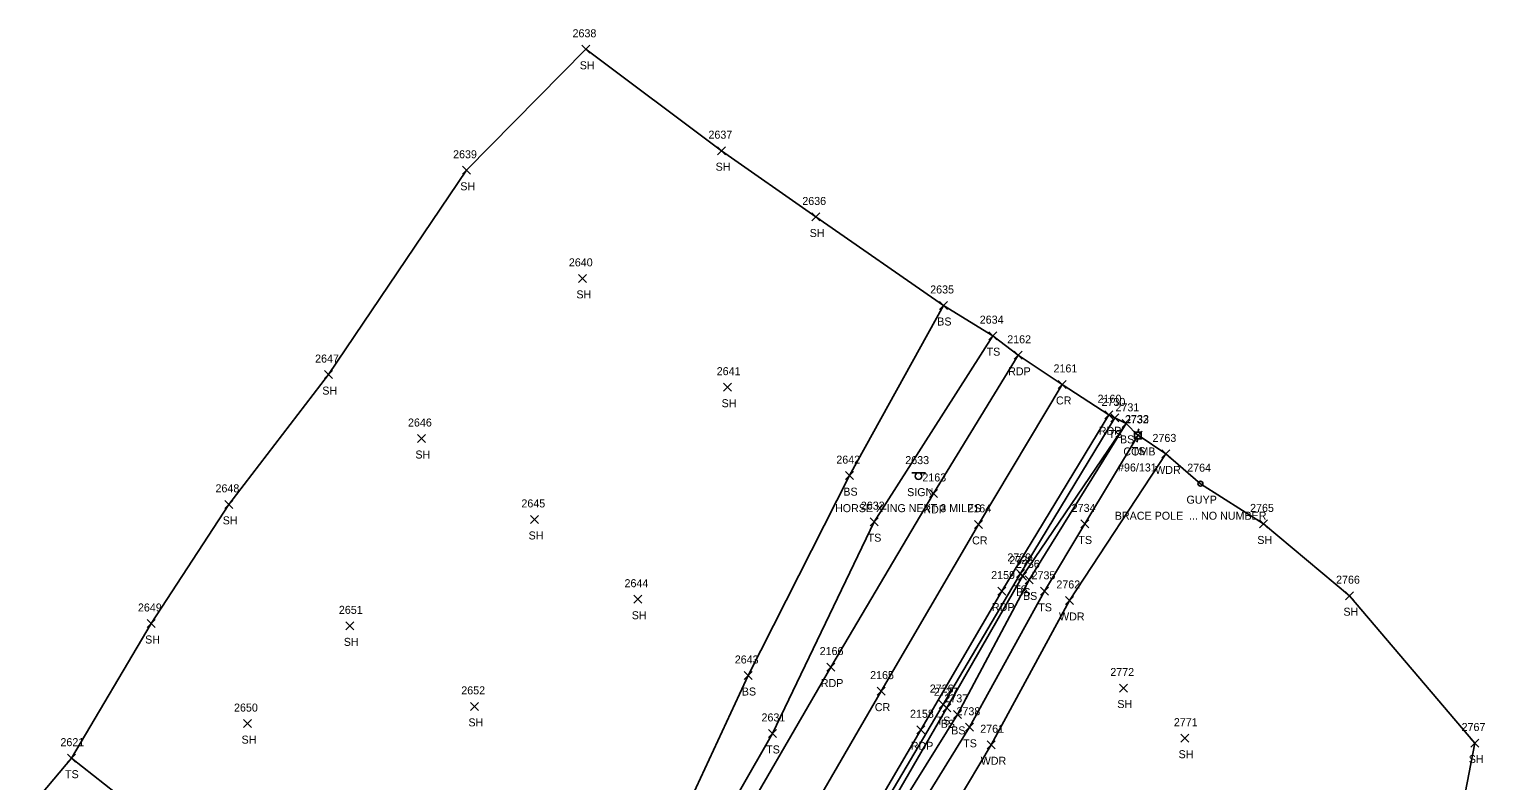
# Model space of a CAD drawing. Extents: x 1633660 to 1636532, y 388643 to 392631.
# Drawn here: x 1634673.8 to 1635037.6, y 389408.7 to 389596.5 of the extents above; entities that cross this region are included whole.
import ezdxf

# ---------------------------------------------------------------- set-up
doc = ezdxf.new("R2010")
doc.units = 0
for name, color, linetype in [('L_A', 7, 'Continuous'), ('L_I', 7, 'Continuous'), ('L_TIC', 7, 'Continuous'), ('LAWA', 7, 'Continuous'), ('LELB', 7, 'Continuous'), ('LSOGP', 7, 'Continuous'), ('P_A', 7, 'Continuous'), ('P_I', 7, 'Continuous'), ('P_TIC', 7, 'Continuous'), ('PET', 7, 'Continuous'), ('PRC', 7, 'Continuous'), ('S_A', 7, 'Continuous'), ('S_C', 7, 'Continuous'), ('S_I', 7, 'Continuous'), ('SSGN', 7, 'Continuous'), ('U_A', 7, 'Continuous'), ('U_C', 7, 'Continuous'), ('U_I', 7, 'Continuous'), ('UP', 7, 'Continuous'), ('UPGW', 7, 'Continuous')]:
    doc.layers.add(name, color=color, linetype=linetype)

msp = doc.modelspace()

# ---------------------------------------------------------------- linework, layer by layer
at = {"layer": 'L_TIC'}
for points in [[(1634811.95, 389590.47), (1634813.95, 389592.47)], [(1634813.95, 389590.47), (1634811.95, 389592.47)], [(1634845.9, 389565.14), (1634847.9, 389567.14)], [(1634847.9, 389565.14), (1634845.9, 389567.14)], [(1634782.1, 389560.25), (1634784.1, 389562.25)], [(1634784.1, 389560.25), (1634782.1, 389562.25)], [(1634869.41, 389548.59), (1634871.41, 389550.59)], [(1634871.41, 389548.59), (1634869.41, 389550.59)], [(1634811.11, 389533.25), (1634813.11, 389535.25)], [(1634813.11, 389533.25), (1634811.11, 389535.25)], [(1634901.32, 389526.48), (1634903.32, 389528.48)], [(1634903.32, 389526.48), (1634901.32, 389528.48)], [(1634913.7, 389518.94), (1634915.7, 389520.94)], [(1634915.7, 389518.94), (1634913.7, 389520.94)], [(1634747.62, 389509.22), (1634749.62, 389511.22)], [(1634749.62, 389509.22), (1634747.62, 389511.22)], [(1634847.4, 389506.07), (1634849.4, 389508.07)], [(1634849.4, 389506.07), (1634847.4, 389508.07)], [(1634944.17, 389498.39), (1634946.17, 389500.39)], [(1634946.17, 389498.39), (1634944.17, 389500.39)], [(1634947, 389497.04), (1634949, 389499.04)], [(1634949, 389497.04), (1634947, 389499.04)], [(1634770.88, 389493.25), (1634772.88, 389495.25)], [(1634772.88, 389493.25), (1634770.88, 389495.25)], [(1634949.98, 389494.12), (1634951.98, 389496.12)], [(1634951.98, 389494.12), (1634949.98, 389496.12)], [(1634956.87, 389489.4), (1634958.87, 389491.4)], [(1634958.87, 389489.4), (1634956.87, 389491.4)], [(1634877.86, 389483.98), (1634879.86, 389485.98)], [(1634879.86, 389483.98), (1634877.86, 389485.98)], [(1634722.73, 389476.81), (1634724.73, 389478.81)], [(1634724.73, 389476.81), (1634722.73, 389478.81)], [(1634799.16, 389473.04), (1634801.16, 389475.04)], [(1634801.16, 389473.04), (1634799.16, 389475.04)], [(1634883.98, 389472.48), (1634885.98, 389474.48)], [(1634885.98, 389472.48), (1634883.98, 389474.48)], [(1634936.63, 389471.92), (1634938.63, 389473.92)], [(1634938.63, 389471.92), (1634936.63, 389473.92)], [(1634981.26, 389471.92), (1634983.26, 389473.92)], [(1634983.26, 389471.92), (1634981.26, 389473.92)], [(1634920.56, 389459.56), (1634922.56, 389461.56)], [(1634922.56, 389459.56), (1634920.56, 389461.56)], [(1634921.04, 389458.89), (1634923.04, 389460.89)], [(1634923.04, 389458.89), (1634921.04, 389460.89)], [(1634922.75, 389457.93), (1634924.75, 389459.93)], [(1634924.75, 389457.93), (1634922.75, 389459.93)], [(1634824.94, 389453.11), (1634826.94, 389455.11)], [(1634826.94, 389453.11), (1634824.94, 389455.11)], [(1634926.6, 389455.09), (1634928.6, 389457.09)], [(1634928.6, 389455.09), (1634926.6, 389457.09)], [(1635002.79, 389453.99), (1635004.79, 389455.99)], [(1635004.79, 389453.99), (1635002.79, 389455.99)], [(1634932.85, 389452.8), (1634934.85, 389454.8)], [(1634934.85, 389452.8), (1634932.85, 389454.8)], [(1634703.35, 389447.05), (1634705.35, 389449.05)], [(1634705.35, 389447.05), (1634703.35, 389449.05)], [(1634752.99, 389446.46), (1634754.99, 389448.46)], [(1634754.99, 389446.46), (1634752.99, 389448.46)], [(1634852.49, 389434.06), (1634854.49, 389436.06)], [(1634854.49, 389434.06), (1634852.49, 389436.06)], [(1634946.28, 389430.93), (1634948.28, 389432.93)], [(1634948.28, 389430.93), (1634946.28, 389432.93)], [(1634784.14, 389426.35), (1634786.14, 389428.35)], [(1634786.14, 389426.35), (1634784.14, 389428.35)], [(1634901.23, 389426.8), (1634903.23, 389428.8)], [(1634903.23, 389426.8), (1634901.23, 389428.8)], [(1634902.19, 389425.99), (1634904.19, 389427.99)], [(1634904.19, 389425.99), (1634902.19, 389427.99)], [(1634904.81, 389424.35), (1634906.81, 389426.35)], [(1634906.81, 389424.35), (1634904.81, 389426.35)], [(1634727.44, 389422.05), (1634729.44, 389424.05)], [(1634729.44, 389422.05), (1634727.44, 389424.05)], [(1634907.84, 389421.13), (1634909.84, 389423.13)], [(1634909.84, 389421.13), (1634907.84, 389423.13)], [(1634858.6, 389419.59), (1634860.6, 389421.59)], [(1634860.6, 389419.59), (1634858.6, 389421.59)], [(1634913.26, 389416.76), (1634915.26, 389418.76)], [(1634915.26, 389416.76), (1634913.26, 389418.76)], [(1634961.6, 389418.4), (1634963.6, 389420.4)], [(1634963.6, 389418.4), (1634961.6, 389420.4)], [(1635034.11, 389417.19), (1635036.11, 389419.19)], [(1635036.11, 389417.19), (1635034.11, 389419.19)], [(1634683.41, 389413.41), (1634685.41, 389415.41)], [(1634685.41, 389413.41), (1634683.41, 389415.41)]]:
    msp.add_lwpolyline(points, dxfattribs=at)
at = {"layer": 'LAWA'}
msp.add_lwpolyline([(1634857.94, 389296.96), (1634848.5, 389300.72), (1634849.29, 389308.34), (1634862.31, 389326.51), (1634880.97, 389363.85), (1634896.76, 389388.41), (1634914.26, 389417.76), (1634933.85, 389453.8), (1634957.87, 389490.4)], dxfattribs=at)
at = {"layer": 'LELB'}
for points in [[(1634902.32, 389527.48), (1634878.86, 389484.98), (1634853.49, 389435.06), (1634838.33, 389402.44), (1634822.14, 389370.68), (1634805.4, 389344.42), (1634781.56, 389307.32)], [(1634760.29, 389263.27), (1634777.7, 389287.05), (1634795.74, 389315.6), (1634812.36, 389341.1), (1634834.55, 389376.8), (1634859.6, 389420.59), (1634884.98, 389473.48), (1634914.7, 389519.94)], [(1634853.67, 389266.92), (1634843.26, 389293.83), (1634835.93, 389308.48), (1634845.9, 389329.19), (1634866.35, 389364.08), (1634881.84, 389393.3), (1634902.23, 389427.8), (1634921.56, 389460.56), (1634945.17, 389499.39)], [(1634836.88, 389309.12), (1634847.11, 389328.98), (1634867.58, 389363.57), (1634883.07, 389392.29), (1634903.19, 389426.99), (1634922.04, 389459.89), (1634948, 389498.04), (1634923.75, 389458.93), (1634905.81, 389425.35), (1634884.7, 389391.31), (1634871.53, 389358.51), (1634859.27, 389332.46), (1634847.91, 389314.24), (1634841.4, 389305.77), (1634847.29, 389289.16), (1634855.14, 389270.43), (1634869.81, 389281.76), (1634885.38, 389291.02)], [(1634950.98, 389495.12), (1634937.63, 389472.92), (1634927.6, 389456.09), (1634908.84, 389422.13), (1634887.64, 389387.9), (1634873.89, 389357.08)], [(1634684.41, 389414.41), (1634714.69, 389390.63), (1634744.94, 389370.41), (1634766.28, 389339.31), (1634779.85, 389306.26)]]:
    msp.add_lwpolyline(points, dxfattribs=at)
at = {"layer": 'LSOGP'}
msp.add_lwpolyline([(1635032.21, 389403.07), (1635035.11, 389418.19), (1635003.79, 389454.99), (1634982.26, 389472.92), (1634966.55, 389482.97), (1634957.87, 389490.4), (1634950.98, 389495.12), (1634950.9, 389495.02), (1634948, 389498.04), (1634945.17, 389499.39), (1634943.65, 389500.19), (1634932, 389507.76), (1634921, 389515.03), (1634914.7, 389519.94), (1634902.32, 389527.48), (1634870.41, 389549.59), (1634846.9, 389566.14), (1634812.95, 389591.47), (1634783.1, 389561.25), (1634748.62, 389510.22), (1634723.73, 389477.81), (1634704.35, 389448.05), (1634684.41, 389414.41), (1634673.84, 389401.81)], dxfattribs=at)
at = {"layer": 'P_TIC'}
for points in [[(1634920, 389514.03), (1634922, 389516.03)], [(1634922, 389514.03), (1634920, 389516.03)], [(1634931, 389506.76), (1634933, 389508.76)], [(1634933, 389506.76), (1634931, 389508.76)], [(1634942.65, 389499.19), (1634944.65, 389501.19)], [(1634944.65, 389499.19), (1634942.65, 389501.19)], [(1634898.8, 389479.53), (1634900.8, 389481.53)], [(1634900.8, 389479.53), (1634898.8, 389481.53)], [(1634910.04, 389471.8), (1634912.04, 389473.8)], [(1634912.04, 389471.8), (1634910.04, 389473.8)], [(1634915.95, 389455.15), (1634917.95, 389457.15)], [(1634917.95, 389455.15), (1634915.95, 389457.15)], [(1634873.19, 389436.17), (1634875.19, 389438.17)], [(1634875.19, 389436.17), (1634873.19, 389438.17)], [(1634885.74, 389430.16), (1634887.74, 389432.16)], [(1634887.74, 389430.16), (1634885.74, 389432.16)], [(1634895.66, 389420.5), (1634897.66, 389422.5)], [(1634897.66, 389420.5), (1634895.66, 389422.5)]]:
    msp.add_lwpolyline(points, dxfattribs=at)
at = {"layer": 'PET'}
for points in [[(1634921, 389515.03), (1634899.8, 389480.53), (1634874.19, 389437.17), (1634846.92, 389390.2), (1634820.4, 389343.78), (1634802.56, 389312.32), (1634782.67, 389284.65), (1634768.75, 389267.29)], [(1634759.68, 389257.14), (1634768.68, 389246.68), (1634778.86, 389234.44), (1634802.84, 389262.52), (1634835.45, 389313), (1634837.67, 389319.49), (1634869.56, 389375.26), (1634896.66, 389421.5), (1634916.95, 389456.15), (1634943.65, 389500.19)]]:
    msp.add_lwpolyline(points, dxfattribs=at)
at = {"layer": 'PRC'}
msp.add_lwpolyline([(1634932, 389507.76), (1634911.04, 389472.8), (1634886.74, 389431.16), (1634857.72, 389381.06), (1634832.11, 389337.09), (1634812.29, 389305.3), (1634793.24, 389277.6), (1634779.17, 389259.21), (1634770.35, 389248.3)], dxfattribs=at)
at = {"layer": 'SSGN'}
for p, q in [((1634894.46, 389485.71), (1634897.8, 389485.71)), ((1634896.11, 389484.88), (1634896.11, 389484.88))]:
    msp.add_line(p, q, dxfattribs=at)
msp.add_circle((1634896.11, 389484.88), 0.833, dxfattribs=at)
at = {"layer": 'UP'}
for p, q in [((1634950.07, 389494.19), (1634950.07, 389495.85)), ((1634950.07, 389495.85), (1634951.73, 389495.85)), ((1634951.15, 389496.69), (1634950.9, 389495.85)), ((1634950.9, 389495.02), (1634950.9, 389495.02)), ((1634951.73, 389495.85), (1634951.73, 389494.19)), ((1634951.73, 389494.19), (1634950.07, 389494.19)), ((1634950.65, 389493.35), (1634950.9, 389494.19))]:
    msp.add_line(p, q, dxfattribs=at)
msp.add_circle((1634950.9, 389495.02), 0.833, dxfattribs=at)
at = {"layer": 'UPGW'}
for radius in [0.625, 0.0833]:
    msp.add_circle((1634966.55, 389482.97), radius, dxfattribs=at)

# ---------------------------------------------------------------- texts
at = {"layer": 'L_A'}
for s, p in [('SH', (1634811.44, 389586.47)), ('SH', (1634845.39, 389561.14)), ('SH', (1634781.59, 389556.25)), ('SH', (1634868.9, 389544.59)), ('SH', (1634810.6, 389529.25)), ('BS', (1634900.76, 389522.48)), ('TS', (1634913.11, 389514.94)), ('SH', (1634747.11, 389505.22)), ('SH', (1634846.89, 389502.07)), ('TS', (1634943.58, 389494.39)), ('BS', (1634946.44, 389493.04)), ('TS', (1634949.39, 389490.12)), ('SH', (1634770.37, 389489.25)), ('WDR', (1634955.23, 389485.4)), ('BS', (1634877.3, 389479.98)), ('SH', (1634722.22, 389472.81)), ('SH', (1634798.65, 389469.04)), ('TS', (1634883.39, 389468.48)), ('TS', (1634936.04, 389467.92)), ('SH', (1634980.75, 389467.92)), ('TS', (1634919.97, 389455.56)), ('BS', (1634920.49, 389454.89)), ('BS', (1634922.19, 389453.93)), ('TS', (1634926.01, 389451.09)), ('SH', (1635002.28, 389449.99)), ('SH', (1634824.43, 389449.11)), ('WDR', (1634931.21, 389448.8)), ('SH', (1634702.84, 389443.05)), ('SH', (1634752.48, 389442.46)), ('BS', (1634851.93, 389430.06)), ('SH', (1634945.77, 389426.93)), ('SH', (1634783.63, 389422.35)), ('TS', (1634900.64, 389422.8)), ('BS', (1634901.63, 389421.99)), ('BS', (1634904.25, 389420.35)), ('SH', (1634726.93, 389418.05)), ('TS', (1634907.25, 389417.13)), ('TS', (1634858.01, 389415.59)), ('SH', (1634961.08, 389414.4)), ('SH', (1635033.6, 389413.19)), ('TS', (1634682.82, 389409.41)), ('WDR', (1634911.63, 389412.76))]:
    msp.add_text(s, height=2, dxfattribs=at).set_placement(p)
at = {"layer": 'L_I'}
for s, p in [('2638', (1634809.64, 389594.47)), ('2637', (1634843.6, 389569.14)), ('2639', (1634779.79, 389564.25)), ('2636', (1634867.05, 389552.59)), ('2640', (1634808.72, 389537.25)), ('2635', (1634899.01, 389530.48)), ('2634', (1634911.39, 389522.94)), ('2647', (1634745.31, 389513.22)), ('2641', (1634845.66, 389510.07)), ('2730', (1634941.83, 389502.39)), ('2731', (1634945.31, 389501.04)), ('2646', (1634768.52, 389497.25)), ('2733', (1634947.72, 389498.12)), ('2763', (1634954.56, 389493.4)), ('2642', (1634875.55, 389487.98)), ('2648', (1634720.42, 389480.81)), ('2645', (1634796.86, 389477.04)), ('2632', (1634881.67, 389476.48)), ('2734', (1634934.37, 389475.92)), ('2765', (1634978.95, 389475.92)), ('2729', (1634918.29, 389463.56)), ('2728', (1634918.78, 389462.89)), ('2736', (1634920.44, 389461.93)), ('2644', (1634822.63, 389457.11)), ('2735', (1634924.34, 389459.09)), ('2762', (1634930.54, 389456.8)), ('2766', (1635000.43, 389457.99)), ('2649', (1634701.04, 389451.05)), ('2651', (1634751.25, 389450.46)), ('2643', (1634850.18, 389438.06)), ('2772', (1634944.02, 389434.93)), ('2652', (1634781.83, 389430.35)), ('2726', (1634898.91, 389430.8)), ('2727', (1634899.93, 389429.99)), ('2737', (1634902.55, 389428.35)), ('2650', (1634725.05, 389426.05)), ('2738', (1634905.58, 389425.13)), ('2631', (1634856.86, 389423.59)), ('2761', (1634911.52, 389420.76)), ('2771', (1634959.9, 389422.4)), ('2767', (1635031.8, 389421.19)), ('2621', (1634681.67, 389417.41))]:
    msp.add_text(s, height=2, dxfattribs=at).set_placement(p)
at = {"layer": 'P_A'}
for s, p in [('RDP', (1634918.49, 389510.03)), ('CR', (1634930.44, 389502.76)), ('RDP', (1634941.14, 389495.19)), ('RDP', (1634897.29, 389475.53)), ('CR', (1634909.48, 389467.8)), ('RDP', (1634914.43, 389451.15)), ('RDP', (1634871.68, 389432.17)), ('CR', (1634885.17, 389426.16)), ('RDP', (1634894.15, 389416.5))]:
    msp.add_text(s, height=2, dxfattribs=at).set_placement(p)
at = {"layer": 'P_I'}
for s, p in [('2162', (1634918.26, 389518.03)), ('2161', (1634929.83, 389510.76)), ('2160', (1634940.83, 389503.19)), ('2163', (1634897.06, 389483.53)), ('2164', (1634908.3, 389475.8)), ('2159', (1634914.25, 389459.15)), ('2166', (1634871.39, 389440.17)), ('2165', (1634884, 389434.16)), ('2158', (1634893.97, 389424.5))]:
    msp.add_text(s, height=2, dxfattribs=at).set_placement(p)
at = {"layer": 'S_A'}
msp.add_text('SIGN', height=2, dxfattribs=at).set_placement((1634893.25, 389479.86))
at = {"layer": 'S_C'}
msp.add_text('HORSE X-ING NEXT 3 MILES', height=2, dxfattribs=at).set_placement((1634875.22, 389475.86))
at = {"layer": 'S_I'}
msp.add_text('2633', height=2, dxfattribs=at).set_placement((1634892.78, 389487.86))
at = {"layer": 'U_A'}
for s, p in [('COMB', (1634947.28, 389490.02)), ('GUYP', (1634963.06, 389477.97))]:
    msp.add_text(s, height=2, dxfattribs=at).set_placement(p)
at = {"layer": 'U_C'}
for s, p in [('#96/131', (1634945.95, 389486.02)), ('BRACE POLE  ... NO NUMBER', (1634945.14, 389473.97))]:
    msp.add_text(s, height=2, dxfattribs=at).set_placement(p)
at = {"layer": 'U_I'}
for s, p in [('2732', (1634947.64, 389498.02)), ('2764', (1634963.24, 389485.97))]:
    msp.add_text(s, height=2, dxfattribs=at).set_placement(p)

doc.saveas('drawing.dxf')
